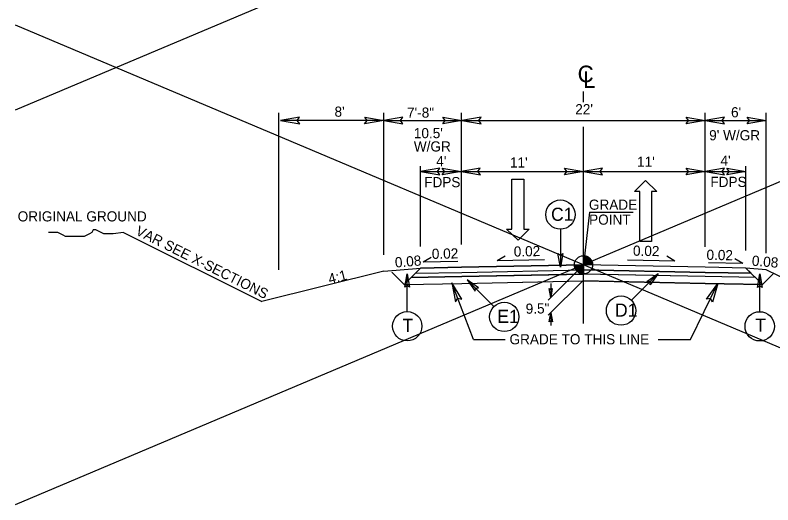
# Model space of a CAD drawing. Extents: x 573732 to 574187, y -53389 to -53257.
# Drawn here: x 574009.4 to 574084, y -53363.5 to -53315.3 of the extents above; entities that cross this region are included whole.
import ezdxf

# ---------------------------------------------------------------- set-up
doc = ezdxf.new("R2010")
doc.units = 0
for name, color, linetype in [('Default', 7, 'Continuous'), ('Old_Level_11', 7, 'Continuous'), ('Prop Dimension', 7, 'Continuous'), ('Prop Lane Arrow CELL', 7, 'Continuous'), ('Prop Shade Light', 7, 'Continuous'), ('Prop Shade Medium', 7, 'Continuous'), ('Typical Grade Point Symbol CELL', 7, 'Continuous'), ('Typical ID Circle CELL', 7, 'Continuous'), ('Typical Pavement Slope CELL', 7, 'Continuous'), ('Typical Pavement Slope Information CELL', 7, 'Continuous'), ('Typical Shoulder Slope CELL', 7, 'Continuous'), ('Typical Shoulder Slope Information CELL', 7, 'Continuous'), ('Typical Slope Point Local CELL', 7, 'Continuous'), ('Typical Terminator CELL', 7, 'Continuous'), ('Typical Text Centerline CELL', 7, 'Continuous'), ('Typical Text General CELL', 7, 'Continuous'), ('Typical Text Grade Point CELL', 7, 'Continuous'), ('Typical Text ID Circle CELL', 7, 'Continuous')]:
    doc.layers.add(name, color=color, linetype=linetype)

msp = doc.modelspace()

# ---------------------------------------------------------------- linework, layer by layer
at = {"layer": 'Default'}
for p, q in [((574121.356, -53277.39), (574009.442, -53324.666)), ((574009.442, -53316.258), (574121.356, -53363.534)), ((574121.356, -53316.258), (574009.442, -53363.534))]:
    msp.add_line(p, q, dxfattribs=at)
at = {"layer": 'Old_Level_11'}
for points in [[(574062.331, -53342.22), (574062.176, -53343.12), (574062.016, -53342.215), (574062.176, -53342.33)], [(574062.021, -53345.52), (574062.176, -53344.62), (574062.336, -53345.525), (574062.176, -53345.41)]]:
    msp.add_lwpolyline(points, close=True, dxfattribs=at)
at = {"layer": 'Prop Dimension'}
for p, q in [((574035.403, -53340.382), (574035.403, -53324.924)), ((574045.733, -53338.915), (574045.733, -53324.924)), ((574053.403, -53337.886), (574053.403, -53324.924)), ((574077.395, -53338.135), (574077.395, -53324.924)), ((574083.395, -53338.748), (574083.395, -53324.924)), ((574045.733, -53325.68), (574035.577, -53325.68)), ((574045.733, -53325.68), (574053.435, -53325.68)), ((574053.435, -53325.68), (574077.395, -53325.68)), ((574077.395, -53325.68), (574083.395, -53325.68)), ((574049.367, -53338.077), (574049.367, -53330.186)), ((574049.367, -53330.713), (574053.366, -53330.713)), ((574053.366, -53330.713), (574065.399, -53330.713)), ((574065.399, -53330.713), (574077.395, -53330.713)), ((574077.395, -53330.713), (574081.395, -53330.713)), ((574081.395, -53338.5), (574081.395, -53330.186)), ((574065.975, -53334.719), (574065.399, -53339.896)), ((574065.975, -53334.719), (574070.295, -53334.719)), ((574065.399, -53339.896), (574061.928, -53343.367)), ((574054.558, -53347.251), (574052.436, -53341.656)), ((574065.399, -53341.397), (574061.928, -53344.867)), ((574062.176, -53341.722), (574062.176, -53343.12)), ((574075.945, -53347.251), (574078.618, -53341.745)), ((574062.176, -53344.62), (574062.176, -53345.874)), ((574054.558, -53347.251), (574057.699, -53347.251)), ((574072.76, -53347.251), (574075.945, -53347.251))]:
    msp.add_line(p, q, dxfattribs=at)
at = {"layer": 'Prop Lane Arrow CELL'}
for p, q in [((574058.357, -53336.375), (574058.357, -53331.475)), ((574058.357, -53331.475), (574059.512, -53331.475)), ((574059.512, -53331.475), (574059.512, -53336.375)), ((574070.429, -53332.683), (574071.514, -53331.58)), ((574071.514, -53331.58), (574072.634, -53332.683)), ((574070.954, -53332.683), (574070.429, -53332.683)), ((574070.954, -53337.583), (574070.954, -53332.683)), ((574072.634, -53332.683), (574072.109, -53332.683)), ((574072.109, -53332.683), (574072.109, -53337.583)), ((574058.952, -53337.477), (574057.832, -53336.375)), ((574057.832, -53336.375), (574058.357, -53336.375)), ((574060.037, -53336.375), (574058.952, -53337.477)), ((574059.512, -53336.375), (574060.037, -53336.375)), ((574072.109, -53337.583), (574070.954, -53337.583))]:
    msp.add_line(p, q, dxfattribs=at)
at = {"layer": 'Prop Shade Light'}
for p, q in [((574049.367, -53340.219), (574048.857, -53340.729)), ((574053.403, -53340.136), (574049.367, -53340.219)), ((574065.399, -53339.896), (574053.403, -53340.136)), ((574053.414, -53340.636), (574065.389, -53340.397)), ((574065.389, -53340.396), (574065.399, -53340.396)), ((574077.395, -53340.136), (574065.399, -53339.896)), ((574065.399, -53340.396), (574065.409, -53340.396)), ((574065.409, -53340.397), (574077.385, -53340.636)), ((574081.395, -53340.218), (574077.395, -53340.136)), ((574081.905, -53340.729), (574081.395, -53340.218)), ((574048.857, -53340.729), (574053.414, -53340.636)), ((574077.385, -53340.636), (574081.905, -53340.729))]:
    msp.add_line(p, q, dxfattribs=at)
for points in [[(574065.389, -53340.397), (574065.389, -53340.396)], [(574065.409, -53340.396), (574065.409, -53340.397)]]:
    msp.add_lwpolyline(points, dxfattribs=at)
at = {"layer": 'Prop Shade Medium'}
for p, q in [((574048.431, -53341.155), (574047.75, -53341.836)), ((574053.422, -53341.053), (574048.431, -53341.155)), ((574082.331, -53341.154), (574077.376, -53341.053)), ((574083.012, -53341.835), (574082.331, -53341.154)), ((574047.75, -53341.836), (574053.436, -53341.719)), ((574053.436, -53341.719), (574065.367, -53341.481)), ((574065.367, -53341.479), (574065.399, -53341.48)), ((574065.399, -53341.48), (574065.431, -53341.479)), ((574065.431, -53341.481), (574077.363, -53341.719)), ((574077.363, -53341.719), (574083.012, -53341.835))]:
    msp.add_line(p, q, dxfattribs=at)
for points in [[(574065.399, -53340.813), (574065.381, -53340.814), (574053.422, -53341.053)], [(574077.376, -53341.053), (574065.417, -53340.814), (574065.399, -53340.813)], [(574065.367, -53341.481), (574065.367, -53341.479)], [(574065.431, -53341.479), (574065.431, -53341.481)]]:
    msp.add_lwpolyline(points, dxfattribs=at)
at = {"layer": 'Typical Grade Point Symbol CELL'}
for p, q in [((574065.399, -53339.896), (574065.399, -53339.001)), ((574064.504, -53339.896), (574065.399, -53339.896)), ((574065.397, -53340.791), (574065.399, -53339.896)), ((574065.399, -53339.896), (574065.397, -53340.791)), ((574066.294, -53339.896), (574065.399, -53339.896))]:
    msp.add_line(p, q, dxfattribs=at)
for points in [[(574065.407, -53339.001), (574065.407, -53339.001), (574065.407, -53339.896)], [(574065.425, -53339.001), (574065.425, -53339.896)], [(574065.443, -53339.003), (574065.443, -53339.896)], [(574065.461, -53339.003), (574065.461, -53339.896)], [(574065.479, -53339.005), (574065.479, -53339.896)], [(574065.497, -53339.007), (574065.497, -53339.896)], [(574065.514, -53339.009), (574065.514, -53339.896)], [(574065.532, -53339.011), (574065.532, -53339.896)], [(574065.55, -53339.013), (574065.55, -53339.896)], [(574065.568, -53339.017), (574065.568, -53339.896)], [(574065.586, -53339.021), (574065.586, -53339.896)], [(574065.604, -53339.025), (574065.604, -53339.896)], [(574065.622, -53339.029), (574065.622, -53339.896)], [(574065.64, -53339.035), (574065.64, -53339.896)], [(574065.658, -53339.039), (574065.658, -53339.896)], [(574065.676, -53339.045), (574065.676, -53339.896)], [(574065.694, -53339.051), (574065.694, -53339.896)], [(574065.711, -53339.057), (574065.711, -53339.896)], [(574065.729, -53339.065), (574065.729, -53339.896)], [(574065.747, -53339.073), (574065.747, -53339.896)], [(574065.765, -53339.081), (574065.765, -53339.896)], [(574065.783, -53339.089), (574065.783, -53339.896)], [(574065.801, -53339.096), (574065.801, -53339.896)], [(574065.819, -53339.106), (574065.819, -53339.896)], [(574065.837, -53339.116), (574065.837, -53339.896)], [(574065.855, -53339.126), (574065.855, -53339.896)], [(574065.873, -53339.136), (574065.873, -53339.896)], [(574065.89, -53339.148), (574065.89, -53339.896)], [(574065.908, -53339.16), (574065.908, -53339.896)], [(574065.926, -53339.174), (574065.926, -53339.896)], [(574065.944, -53339.186), (574065.944, -53339.896)], [(574065.962, -53339.2), (574065.962, -53339.896)], [(574065.98, -53339.216), (574065.98, -53339.896)], [(574065.998, -53339.232), (574065.998, -53339.896)], [(574066.016, -53339.248), (574066.016, -53339.896)], [(574066.034, -53339.266), (574066.034, -53339.896)], [(574066.052, -53339.284), (574066.052, -53339.896)], [(574066.069, -53339.303), (574066.069, -53339.896)], [(574066.087, -53339.325), (574066.087, -53339.896)], [(574066.105, -53339.347), (574066.105, -53339.896)], [(574066.123, -53339.371), (574066.123, -53339.896)], [(574066.141, -53339.397), (574066.141, -53339.896)], [(574066.159, -53339.425), (574066.159, -53339.896)], [(574066.177, -53339.455), (574066.177, -53339.896)], [(574066.195, -53339.486), (574066.195, -53339.896)], [(574066.213, -53339.524), (574066.213, -53339.896)], [(574066.231, -53339.566), (574066.231, -53339.896)], [(574066.249, -53339.616), (574066.249, -53339.896)], [(574066.266, -53339.677), (574066.266, -53339.896)], [(574066.284, -53339.769), (574066.284, -53339.896)], [(574064.508, -53339.896), (574064.508, -53339.994)], [(574064.526, -53339.896), (574064.526, -53340.099)], [(574064.544, -53339.896), (574064.544, -53340.163)], [(574064.562, -53339.896), (574064.562, -53340.217)], [(574064.58, -53339.896), (574064.58, -53340.258)], [(574064.597, -53339.896), (574064.597, -53340.296)], [(574064.615, -53339.896), (574064.615, -53340.33)], [(574064.633, -53339.896), (574064.633, -53340.362)], [(574064.651, -53339.896), (574064.651, -53340.39)], [(574064.669, -53339.896), (574064.669, -53340.415)], [(574064.687, -53339.896), (574064.687, -53340.439)], [(574064.705, -53339.896), (574064.705, -53340.461)], [(574064.723, -53339.896), (574064.723, -53340.483)], [(574064.741, -53339.896), (574064.741, -53340.503)], [(574064.759, -53339.896), (574064.759, -53340.523)], [(574064.776, -53339.896), (574064.776, -53340.541)], [(574064.794, -53339.896), (574064.794, -53340.557)], [(574064.812, -53339.896), (574064.812, -53340.573)], [(574064.83, -53339.896), (574064.83, -53340.588)], [(574064.848, -53339.896), (574064.848, -53340.602)], [(574064.866, -53339.896), (574064.866, -53340.616)], [(574064.884, -53339.896), (574064.884, -53340.628)], [(574064.902, -53339.896), (574064.902, -53340.64)], [(574064.92, -53339.896), (574064.92, -53340.652)], [(574064.938, -53339.896), (574064.938, -53340.664)], [(574064.956, -53339.896), (574064.956, -53340.674)], [(574064.973, -53339.896), (574064.973, -53340.684)], [(574064.991, -53339.896), (574064.991, -53340.694)], [(574065.009, -53339.896), (574065.009, -53340.702)], [(574065.027, -53339.896), (574065.027, -53340.71)], [(574065.045, -53339.896), (574065.045, -53340.718)], [(574065.063, -53339.896), (574065.063, -53340.726)], [(574065.081, -53339.896), (574065.081, -53340.734)], [(574065.099, -53339.896), (574065.099, -53340.74)], [(574065.117, -53339.896), (574065.117, -53340.746)], [(574065.135, -53339.896), (574065.135, -53340.752)], [(574065.152, -53339.896), (574065.152, -53340.756)], [(574065.17, -53339.896), (574065.17, -53340.762)], [(574065.188, -53339.896), (574065.188, -53340.766)], [(574065.206, -53339.896), (574065.206, -53340.77)], [(574065.224, -53339.896), (574065.224, -53340.774)], [(574065.242, -53339.896), (574065.242, -53340.777)], [(574065.26, -53339.896), (574065.26, -53340.779)], [(574065.278, -53339.896), (574065.278, -53340.783)], [(574065.296, -53339.896), (574065.296, -53340.785)], [(574065.314, -53339.896), (574065.314, -53340.787)], [(574065.331, -53339.896), (574065.331, -53340.789)], [(574065.349, -53339.896), (574065.349, -53340.789)], [(574065.367, -53339.896), (574065.367, -53340.791)], [(574065.385, -53339.896), (574065.385, -53340.791), (574065.385, -53340.791)]]:
    msp.add_lwpolyline(points, dxfattribs=at)
msp.add_circle((574065.398, -53339.896), 0.895, dxfattribs=at)
for start, end in [(359.99048, 89.99048), (179.99048, 269.99048)]:
    msp.add_arc((574065.398, -53339.896), 0.895, start, end, dxfattribs=at)
at = {"layer": 'Typical ID Circle CELL'}
for p, q in [((574063.123, -53336.395), (574063.123, -53340.123)), ((574048.041, -53344.497), (574048.041, -53340.769)), ((574070.113, -53343.387), (574072.75, -53340.751)), ((574082.747, -53344.511), (574082.747, -53340.783)), ((574056.584, -53344.005), (574053.947, -53341.369))]:
    msp.add_line(p, q, dxfattribs=at)
for centre in [(574063.123, -53334.953), (574057.603, -53345.025), (574069.094, -53344.408), (574048.041, -53345.939), (574082.747, -53345.953)]:
    msp.add_circle(centre, 1.443, dxfattribs=at)
at = {"layer": 'Typical Pavement Slope CELL'}
for p, q in [((574053.403, -53340.136), (574065.399, -53339.896)), ((574053.413, -53340.636), (574065.409, -53340.396)), ((574077.385, -53340.636), (574065.389, -53340.396)), ((574077.395, -53340.136), (574065.399, -53339.896)), ((574053.422, -53341.053), (574065.417, -53340.813)), ((574077.376, -53341.053), (574065.381, -53340.813)), ((574053.435, -53341.719), (574065.431, -53341.479)), ((574077.363, -53341.719), (574065.367, -53341.479))]:
    msp.add_line(p, q, dxfattribs=at)
at = {"layer": 'Typical Pavement Slope Information CELL'}
for p, q in [((574056.904, -53339.47), (574057.687, -53338.997)), ((574074.378, -53339.531), (574073.595, -53339.057)), ((574049.619, -53339.604), (574050.402, -53339.131)), ((574049.619, -53339.604), (574053.014, -53339.536)), ((574056.904, -53339.47), (574061.564, -53339.377)), ((574074.378, -53339.531), (574069.718, -53339.438)), ((574081.094, -53339.776), (574077.699, -53339.708)), ((574081.094, -53339.776), (574080.311, -53339.303))]:
    msp.add_line(p, q, dxfattribs=at)
at = {"layer": 'Typical Shoulder Slope CELL'}
for p, q in [((574045.742, -53340.521), (574049.367, -53340.219)), ((574047.75, -53341.836), (574049.367, -53340.219)), ((574049.367, -53340.219), (574053.403, -53340.136)), ((574081.395, -53340.218), (574077.395, -53340.136)), ((574083.395, -53340.385), (574081.395, -53340.218)), ((574083.012, -53341.835), (574081.395, -53340.218)), ((574047.75, -53341.836), (574046.518, -53340.604)), ((574048.431, -53341.155), (574053.422, -53341.053)), ((574048.857, -53340.729), (574053.414, -53340.636)), ((574082.331, -53341.154), (574077.376, -53341.053)), ((574081.905, -53340.729), (574077.385, -53340.636)), ((574083.012, -53341.835), (574084.106, -53340.74)), ((574047.75, -53341.836), (574053.436, -53341.719)), ((574083.012, -53341.835), (574077.362, -53341.719))]:
    msp.add_line(p, q, dxfattribs=at)
at = {"layer": 'Typical Slope Point Local CELL'}
for p, q in [((574020.121, -53336.713), (574033.738, -53343.521)), ((574045.738, -53340.521), (574033.738, -53343.521)), ((574105.895, -53351.635), (574083.395, -53340.385))]:
    msp.add_line(p, q, dxfattribs=at)
msp.add_lwpolyline([(574020.121, -53336.713), (574019.084, -53336.842), (574018.825, -53336.842), (574018.435, -53336.842), (574018.176, -53336.842), (574017.916, -53336.713), (574017.657, -53336.583), (574017.398, -53336.453), (574017.138, -53336.453), (574017.008, -53336.713), (574016.749, -53336.842), (574016.49, -53336.972), (574016.23, -53337.101), (574015.971, -53337.101), (574015.712, -53337.101), (574015.452, -53337.101), (574015.193, -53337.101), (574014.934, -53337.101), (574014.674, -53337.101), (574014.415, -53337.101), (574014.156, -53336.972), (574013.896, -53336.842), (574013.637, -53336.713), (574013.247, -53336.713), (574012.988, -53336.713), (574012.729, -53336.713)], dxfattribs=at)
at = {"layer": 'Typical Terminator CELL'}
for points in [[(574037.451, -53325.357), (574035.577, -53325.68), (574037.462, -53326.013), (574037.222, -53325.68)], [(574043.859, -53325.357), (574045.733, -53325.68), (574043.848, -53326.013), (574044.088, -53325.68)], [(574047.608, -53325.357), (574045.733, -53325.68), (574047.619, -53326.013), (574047.379, -53325.68)], [(574051.56, -53325.357), (574053.435, -53325.68), (574051.55, -53326.013), (574051.789, -53325.68)], [(574055.31, -53325.357), (574053.435, -53325.68), (574055.32, -53326.013), (574055.08, -53325.68)], [(574075.52, -53325.357), (574077.395, -53325.68), (574075.51, -53326.013), (574075.749, -53325.68)], [(574079.269, -53325.357), (574077.395, -53325.68), (574079.28, -53326.013), (574079.04, -53325.68)], [(574081.52, -53325.357), (574083.395, -53325.68), (574081.51, -53326.013), (574081.749, -53325.68)], [(574051.242, -53330.39), (574049.367, -53330.713), (574051.252, -53331.046), (574051.013, -53330.713)], [(574051.491, -53330.39), (574053.366, -53330.713), (574051.481, -53331.046), (574051.721, -53330.713)], [(574055.241, -53330.39), (574053.366, -53330.713), (574055.251, -53331.046), (574055.012, -53330.713)], [(574063.524, -53330.39), (574065.399, -53330.713), (574063.514, -53331.046), (574063.754, -53330.713)], [(574067.274, -53330.39), (574065.399, -53330.713), (574067.284, -53331.046), (574067.045, -53330.713)], [(574075.52, -53330.39), (574077.395, -53330.713), (574075.51, -53331.046), (574075.749, -53330.713)], [(574079.269, -53330.39), (574077.395, -53330.713), (574079.28, -53331.046), (574079.04, -53330.713)], [(574079.52, -53330.39), (574081.395, -53330.713), (574079.51, -53331.046), (574079.749, -53330.713)], [(574063.353, -53338.787), (574063.123, -53340.123), (574062.885, -53338.78), (574063.123, -53338.951)], [(574047.811, -53342.104), (574048.041, -53340.769), (574048.279, -53342.112), (574048.041, -53341.941)], [(574071.643, -53341.533), (574072.75, -53340.751), (574071.968, -53341.869), (574071.921, -53341.58)], [(574082.517, -53342.119), (574082.747, -53340.783), (574082.984, -53342.126), (574082.747, -53341.956)], [(574053.42, -53343.285), (574052.436, -53341.656), (574052.812, -53343.533), (574053.036, -53343.189)], [(574055.054, -53342.15), (574053.947, -53341.369), (574054.729, -53342.486), (574054.776, -53342.198)], [(574077.509, -53343.29), (574078.618, -53341.745), (574078.095, -53343.586), (574077.899, -53343.225)]]:
    msp.add_lwpolyline(points, close=True, dxfattribs=at)
at = {"layer": 'Typical Text Centerline CELL'}
for p, q in [((574065.399, -53323.868), (574065.399, -53322.814)), ((574065.399, -53345.678), (574065.399, -53326.294))]:
    msp.add_line(p, q, dxfattribs=at)

# ---------------------------------------------------------------- texts
at = {"layer": 'Typical Pavement Slope Information CELL'}
for s, rotation, p in [("22'", 360, (574064.588, -53325.072)), ("8'", 360, (574040.887, -53325.311)), ('7\'-8"', 360, (574048.028, -53325.405)), ("6'", 360, (574079.927, -53325.372)), ("10.5'", 360, (574048.697, -53327.425)), ("9' W/GR", 360, (574077.774, -53327.632)), ('W/GR', 360, (574048.697, -53328.736)), ("4'", 360, (574050.904, -53330.181)), ("11'", 360, (574058.158, -53330.313)), ("11'", 360, (574070.673, -53330.244)), ("4'", 360, (574078.888, -53330.131)), ('FDPS', 360, (574049.715, -53332.25)), ('FDPS', 360, (574077.893, -53332.226)), ('ORIGINAL GROUND', 360, (574009.69, -53335.623)), ('0.02', 1.14574, (574058.544, -53339.087)), ('0.02', 358.85426, (574070.264, -53338.995))]:
    msp.add_text(s, height=1, rotation=rotation, dxfattribs=at).set_placement(p)
at = {"layer": 'Typical Shoulder Slope Information CELL'}
for s, rotation, p in [('0.02', 1.14574, (574050.477, -53339.316)), ('0.08', 4.76147, (574046.875, -53340.169)), ('0.02', 358.85426, (574077.502, -53339.402)), ('0.08', 355.23853, (574081.944, -53339.97)), ('9.5"', 1.14574, (574059.719, -53344.719))]:
    msp.add_text(s, height=1, rotation=rotation, dxfattribs=at).set_placement(p)
at = {"layer": 'Typical Slope Point Local CELL'}
for s, rotation, p in [('VAR SEE X-SECTIONS', 333.43495, (574021.214, -53336.876)), ('4:1', 14.03624, (574040.403, -53341.796))]:
    msp.add_text(s, height=1, rotation=rotation, dxfattribs=at).set_placement(p)
at = {"layer": 'Typical Text Centerline CELL'}
msp.add_text('C', height=1.64, dxfattribs=at).set_placement((574064.819, -53321.916))
msp.add_text('L', height=1.641, rotation=359.9469, dxfattribs=at).set_placement((574065.364, -53322.476))
at = {"layer": 'Typical Text General CELL'}
msp.add_text('GRADE TO THIS LINE', height=1, dxfattribs=at).set_placement((574058.116, -53347.725))
at = {"layer": 'Typical Text Grade Point CELL'}
for s, p in [('GRADE', (574065.932, -53334.473)), ('POINT', (574065.953, -53335.945))]:
    msp.add_text(s, height=1, dxfattribs=at).set_placement(p)
at = {"layer": 'Typical Text ID Circle CELL'}
for s, p in [('C1', (574062.204, -53335.562)), ('D1', (574068.503, -53345.002)), ('T ', (574047.575, -53346.499)), ('T ', (574082.314, -53346.481))]:
    msp.add_text(s, height=1.2912, dxfattribs=at).set_placement(p)
msp.add_text('E1', height=1.2912, rotation=360, dxfattribs=at).set_placement((574056.922, -53345.619))

doc.saveas('drawing.dxf')
